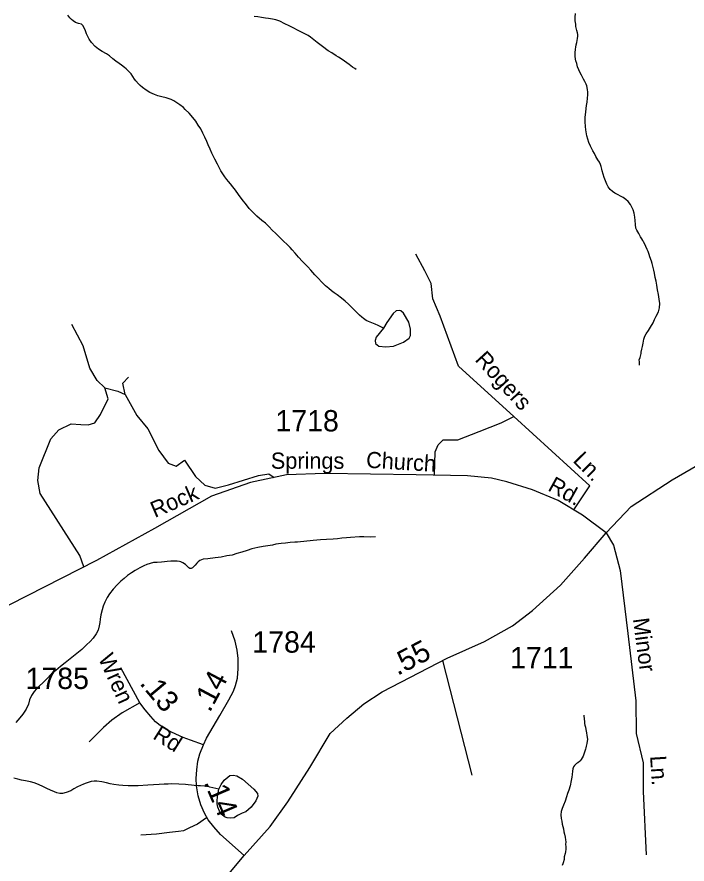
# Model space of a CAD drawing. Extents: x 2056842 to 2160602, y 826753 to 1016856.
# Drawn here: x 2112934 to 2116862, y 842001 to 846969 of the extents above; entities that cross this region are included whole.
import ezdxf

# ---------------------------------------------------------------- set-up
doc = ezdxf.new("R2010")
doc.units = 0
for name, color, linetype in [('Exist Hydrographic Misc Water Feature', 7, 'Continuous'), ('Exist Hydrographic Pond Under 1500 Sq Ft', 7, 'Continuous'), ('Exist Road Non-System Type 51', 7, 'Continuous'), ('Exist Road Non-System Type 51 Label', 7, 'Continuous'), ('Exist Road Secondary Mileage Hundredths English Label', 7, 'Continuous'), ('Exist Road Secondary Type 51 Attributed', 7, 'Continuous'), ('Exist Road Secondary Type 51 Label', 7, 'Continuous'), ('Exist Road Secondary Type 51 Number Label', 7, 'Continuous')]:
    doc.layers.add(name, color=color, linetype=linetype)

msp = doc.modelspace()

# ---------------------------------------------------------------- linework, layer by layer
at = {"layer": 'Exist Hydrographic Misc Water Feature'}
for points in [[(2113411.9, 846779.1), (2113392.1, 846796.3), (2113371.3, 846818.1), (2113357.2, 846838.1), (2113349, 846854.7), (2113341, 846870.5), (2113335.3, 846886.5), (2113328.9, 846904.5), (2113320.5, 846918.7), (2113312.9, 846926), (2113294.2, 846929.6), (2113276.6, 846935.9), (2113262.7, 846946.2), (2113254.1, 846953.5), (2113244.2, 846963.5), (2113232.5, 846979.5)], [(2114922.4, 846659.8), (2114914.6, 846665.9), (2114902.1, 846673.5), (2114882, 846689.5), (2114854.3, 846709.9), (2114839.7, 846719.1), (2114819.8, 846733.4), (2114805.5, 846741.3), (2114779.6, 846759), (2114759.5, 846770.9), (2114724.9, 846796.1), (2114693.1, 846819.5), (2114674.9, 846834.1), (2114654.6, 846850.1), (2114640.8, 846859.5), (2114610.3, 846875.5), (2114582.4, 846889.5), (2114554.3, 846904.7), (2114530.1, 846916.5), (2114504.1, 846928.5), (2114474.5, 846943.1), (2114451.8, 846951.8), (2114432.9, 846955.5), (2114409.7, 846959.4), (2114391.7, 846961.4), (2114367.7, 846965), (2114345.8, 846968.7), (2114325.7, 846971)], [(2116215.4, 846694.9), (2116211.3, 846711.3), (2116209.3, 846721.4), (2116207, 846739.2), (2116206.6, 846757.5), (2116208.7, 846779.5), (2116210.5, 846790.9), (2116212.5, 846804.9), (2116215.4, 846819.4), (2116218.1, 846830.8), (2116219.9, 846841.5), (2116222.2, 846855.3), (2116221.8, 846865.9), (2116219.9, 846875.2), (2116215.8, 846889.1), (2116211.3, 846913), (2116209.5, 846927), (2116207.4, 846945.2), (2116206.8, 846967.2), (2116208.9, 846989.2)], [(2115082.2, 845143.7), (2115067.7, 845151.2), (2115051.5, 845158.9), (2115033.7, 845166.5), (2115013.8, 845174.4), (2114995.4, 845182), (2114981.8, 845189), (2114966, 845199.8), (2114955.6, 845208.3), (2114943.1, 845220), (2114931.2, 845231.9), (2114912.7, 845249.3), (2114896.7, 845265.1), (2114878.5, 845283.7), (2114858.6, 845301.4), (2114836.4, 845318.9), (2114812, 845338.4), (2114794, 845350.1), (2114777.8, 845363), (2114761.8, 845376.5), (2114743.6, 845392.2), (2114721.4, 845414.2), (2114699.3, 845437.4), (2114681.2, 845456), (2114656.8, 845483.7), (2114639, 845503.4), (2114624.6, 845519.3), (2114608.4, 845535.2), (2114584.2, 845560.4), (2114566, 845583), (2114547.7, 845602), (2114535.8, 845616.4), (2114517.4, 845634.2), (2114497.5, 845654.3), (2114479, 845671.7), (2114451.2, 845697.8), (2114431.1, 845717.9), (2114412.6, 845736.9), (2114390.5, 845759), (2114370.6, 845774.9), (2114340.4, 845801), (2114318.1, 845822.6), (2114296.3, 845845.4), (2114279.5, 845866.2), (2114255.3, 845897.9), (2114232.8, 845927.7), (2114214.7, 845951.9), (2114200.6, 845971.9), (2114186.4, 845989.4), (2114174.5, 846003.8), (2114164.5, 846015.1), (2114152.2, 846031.2), (2114140.1, 846049.6), (2114130.2, 846066.9), (2114119.6, 846085.2), (2114109.7, 846104.9), (2114093.5, 846135), (2114076.9, 846170.4), (2114067.1, 846192.9), (2114054.6, 846218.4), (2114046.6, 846238.3), (2114036.3, 846264.1), (2114024.2, 846287.9), (2114011.7, 846312.1), (2113997.4, 846333.8), (2113983.2, 846357.8), (2113965.2, 846379.6), (2113943.2, 846403.6), (2113920.9, 846425.7), (2113911, 846437.3), (2113888.5, 846453.3), (2113872.3, 846465.1), (2113854.7, 846477.1), (2113838, 846484.5), (2113808.3, 846494.3), (2113784.1, 846499.5), (2113760.5, 846506), (2113740, 846513.9), (2113714, 846525.6), (2113691.6, 846539.5), (2113669.7, 846555.4), (2113656, 846567.2), (2113645.7, 846577.3), (2113631.6, 846594.8), (2113623.6, 846604.6), (2113613.1, 846618.8), (2113603.5, 846634.8), (2113594.2, 846645.5), (2113580.9, 846658.1), (2113574.8, 846663.9), (2113564.7, 846672.4), (2113546.5, 846686), (2113532.9, 846695.8), (2113514.3, 846709.6), (2113496.2, 846723.7), (2113476.5, 846739.7), (2113458.5, 846751.8), (2113433.9, 846765.2), (2113411.9, 846779.1)], [(2116582.9, 844926.2), (2116582.9, 844945.7), (2116582.7, 844958.2), (2116586.8, 844971.9), (2116592.5, 844994.1), (2116594.4, 845002.3), (2116598, 845020), (2116601.7, 845036.5), (2116605.8, 845056.2), (2116609.5, 845078.3), (2116615.5, 845096.1), (2116623.5, 845110.7), (2116636, 845130.3), (2116649.1, 845150.3), (2116663, 845174.5), (2116672.3, 845195), (2116682.3, 845214.6), (2116694.2, 845239.6), (2116700, 845263.5), (2116702, 845288.7), (2116699.8, 845313.4), (2116695.4, 845341.3), (2116688.9, 845368.6), (2116684.8, 845394.8), (2116680.7, 845418.9), (2116676.4, 845441.1), (2116672.1, 845466.5), (2116667.8, 845484.6), (2116657.7, 845522.6), (2116653.6, 845536.7), (2116645, 845562.3), (2116641.1, 845574.7), (2116634.8, 845592.7), (2116628.8, 845604.5), (2116620.8, 845622.8), (2116614.2, 845636.7), (2116606.7, 845650.1), (2116602.6, 845658.4), (2116598.3, 845666.7), (2116590.3, 845679.7), (2116584.3, 845690), (2116580, 845699.1), (2116574.3, 845708.1), (2116568.1, 845718), (2116563, 845730.5), (2116559.7, 845751.7), (2116557.4, 845775.6), (2116555.4, 845793.8), (2116552.1, 845817.8), (2116547, 845838), (2116539, 845853.8), (2116530.8, 845868.1), (2116518.1, 845887.1), (2116504.3, 845898.8), (2116488.1, 845909), (2116472.6, 845916.7), (2116457.8, 845925.4), (2116439.7, 845934.6), (2116426.2, 845944.8), (2116412.7, 845957.4), (2116400.6, 845972.6), (2116392.4, 845988.9), (2116384, 846007.2), (2116376.6, 846027.4), (2116370.4, 846046.1), (2116364.9, 846066.8), (2116362.6, 846076.5), (2116359.6, 846090.8), (2116354.4, 846103.7), (2116348.5, 846116.4), (2116340.3, 846130.2), (2116328.2, 846150.3), (2116319, 846168), (2116310.8, 846182.6), (2116295.8, 846210), (2116286.8, 846233.3), (2116281.2, 846251.1), (2116275.1, 846272), (2116268.7, 846305.8), (2116266.5, 846325.6), (2116264.4, 846353.6), (2116266.1, 846381.3), (2116270, 846409.9), (2116271.8, 846431.1), (2116273.7, 846449.9), (2116277.3, 846469.6), (2116279.4, 846491.7), (2116280.8, 846511.3), (2116280.2, 846527.6), (2116278.4, 846542.5), (2116274.5, 846564.2), (2116270.4, 846575.4), (2116264.2, 846589.7), (2116256, 846603.9), (2116247.8, 846619.3), (2116243.9, 846626.8), (2116233.5, 846645.1), (2116227.9, 846657.7), (2116221.2, 846675.7), (2116215.4, 846694.9)], [(2115082.2, 845143.7), (2115039.8, 845090.4), (2115033.6, 845070.3), (2115036.1, 845052.7), (2115056.2, 845038.9), (2115096.3, 845033.9), (2115141.5, 845038.9), (2115199.3, 845061.5), (2115233.2, 845085.4), (2115240.7, 845100.4), (2115242, 845136.9), (2115230.7, 845178.3), (2115199.3, 845232.4), (2115185.5, 845244.9), (2115176.7, 845247.4), (2115157.9, 845244.9), (2115139, 845228.6), (2115102.6, 845177.1), (2115082.2, 845143.7)], [(2115035.8, 843918.9), (2115007.7, 843918.7), (2114967.7, 843920.3), (2114941.6, 843920.2), (2114890, 843915.4), (2114865.8, 843913.4), (2114839.5, 843911.3), (2114814.1, 843908.7), (2114787.6, 843906.6), (2114748.3, 843904.5), (2114713.8, 843901.5), (2114669.7, 843897.6), (2114578.3, 843888.8), (2114564.1, 843888.5), (2114536.5, 843885.8), (2114508.4, 843882.4), (2114482.1, 843880.3), (2114452, 843875.9), (2114431.3, 843871.3), (2114404.6, 843867.2), (2114376.7, 843862.5), (2114346.4, 843857), (2114310.7, 843848.6), (2114282.8, 843840.2), (2114252.7, 843830.2), (2114222.9, 843821.7), (2114195, 843813), (2114164.9, 843807.4), (2114131.1, 843800.8), (2114097, 843796.1), (2114053.6, 843789.8), (2114025.3, 843788), (2114007.2, 843781.8), (2113997.4, 843773.9), (2113989.2, 843765.8), (2113979.5, 843753.5), (2113963.7, 843737.6), (2113955.3, 843733.7), (2113948.4, 843734.7), (2113941.8, 843738.9), (2113931.8, 843747.3), (2113921.5, 843757.4), (2113907.4, 843766.5), (2113895.1, 843772.8), (2113887.3, 843774.4), (2113873.7, 843776.5), (2113856.3, 843776.6), (2113835.4, 843776.1), (2113815.3, 843775.9), (2113799.3, 843773.9), (2113781, 843771.8), (2113755.6, 843769.5), (2113735.5, 843768.6), (2113715, 843763.1), (2113695.3, 843757.2), (2113677.5, 843749.3), (2113655.3, 843738.9), (2113627.9, 843722.4), (2113606.1, 843708.2), (2113582.1, 843692), (2113562.5, 843675.9), (2113542.4, 843659.5), (2113520.8, 843637.6), (2113498.5, 843613.3), (2113476.7, 843585), (2113463.4, 843563.5), (2113449.5, 843536.4), (2113439.6, 843513.1), (2113433.9, 843490.9), (2113426.1, 843462.4), (2113422.2, 843436.2), (2113420.6, 843418.2), (2113416.5, 843398.5), (2113411.1, 843372.6), (2113399, 843350.5), (2113381, 843326.4), (2113363.6, 843306.3), (2113342, 843286.1), (2113313.7, 843259.5), (2113276.2, 843227.5), (2113246.5, 843205.2), (2113216.9, 843180.5), (2113189.1, 843158.7), (2113161.2, 843136.6), (2113137.4, 843116.6), (2113109.7, 843087.6), (2113085.5, 843063.2), (2113065.8, 843046), (2113048, 843028.7), (2113034.2, 843012.9), (2113020.1, 842989.2), (2113008.6, 842963.3), (2113001.2, 842938.9), (2112987.3, 842908.9), (2112969.2, 842880.4), (2112951.6, 842858.7), (2112927.8, 842830.3)], [(2116258.1, 842873.2), (2116259.7, 842847.8), (2116260.3, 842838), (2116262, 842825.5), (2116264.2, 842815.9), (2116266.5, 842803.4), (2116268.7, 842789.2), (2116272.6, 842769.5), (2116274.7, 842753.9), (2116276.9, 842744.2), (2116278, 842731.9), (2116276.9, 842721.1), (2116275.1, 842707.9), (2116273.2, 842699.3), (2116271.6, 842691.8), (2116269.6, 842682), (2116267.7, 842673.7), (2116263.6, 842661.8), (2116257.9, 842645.2), (2116252.9, 842633.8), (2116247.4, 842623.2), (2116242.5, 842613.5), (2116236.3, 842605.5), (2116232.4, 842601.6), (2116222.2, 842593.4), (2116214.6, 842589.7), (2116206.8, 842583.2), (2116202.7, 842579.3), (2116196.8, 842571.3), (2116192.9, 842558.9), (2116190.6, 842545), (2116189.2, 842525.4), (2116187.5, 842510.6), (2116183.4, 842491), (2116177.7, 842459), (2116169.7, 842434.6), (2116162.5, 842414.2), (2116156, 842394.9), (2116147.5, 842370.2), (2116138.9, 842346.7), (2116130.9, 842326.5), (2116125.4, 842308.6), (2116123.1, 842290.3), (2116125.4, 842268.5), (2116127.5, 842252.7), (2116130.1, 842235.3), (2116133.6, 842220.6), (2116138.1, 842206.5), (2116140.8, 842189.9), (2116144.7, 842175.1), (2116148.4, 842158.7), (2116150.4, 842142.1), (2116151.4, 842130.7), (2116150.8, 842114.5), (2116151, 842102.7), (2116151.2, 842088.9), (2116149, 842072.6), (2116147.3, 842062.7), (2116143, 842042.2), (2116141.6, 842028.2), (2116135.7, 842008), (2116133.8, 842002.2), (2116129.7, 841992.7)], [(2114117.4, 842439.2), (2114064.8, 842451.9), (2114055.2, 842454.6), (2114046.8, 842456.3), (2114032.8, 842458.4), (2114009.3, 842459.6), (2113994.7, 842459.7), (2113973, 842461), (2113957, 842463), (2113938.7, 842464.9), (2113922.9, 842466.9), (2113882.7, 842468.6), (2113838.9, 842470.3), (2113821, 842469.8), (2113796.6, 842469.8), (2113767.1, 842467.8), (2113734.7, 842465), (2113701.1, 842462.4), (2113645.1, 842460.3), (2113622.9, 842460), (2113586.9, 842460.2), (2113555.3, 842461.4), (2113531.1, 842463.8), (2113502.8, 842467.7), (2113481.3, 842471.4), (2113458.7, 842476.4), (2113432, 842482.1), (2113402.5, 842486.1), (2113386.7, 842486.1), (2113369.5, 842484.2), (2113340.8, 842475.6), (2113325, 842469.5), (2113307.2, 842461.6), (2113288.7, 842453.1), (2113267.6, 842441.3), (2113249.3, 842431), (2113223.3, 842420.8), (2113200.7, 842414.9), (2113185.8, 842414.3), (2113167.3, 842418.7), (2113153.4, 842423.7), (2113131, 842433.1), (2113109.5, 842443.7), (2113089, 842453.7), (2113061.1, 842467.6), (2113034.9, 842477.3), (2113012.9, 842483.5), (2112984.8, 842488.9), (2112960.8, 842492.6), (2112938.7, 842498), (2112916.7, 842504.1)]]:
    msp.add_lwpolyline(points, dxfattribs=at)
at = {"layer": 'Exist Hydrographic Pond Under 1500 Sq Ft'}
msp.add_lwpolyline([(2114109.4, 842396), (2114117.4, 842439), (2114131, 842467.3), (2114149.1, 842492.2), (2114169.4, 842510.3), (2114181.9, 842520.5), (2114201.1, 842522.8), (2114223.8, 842518.2), (2114256.6, 842497.9), (2114322.3, 842440.2), (2114344.9, 842414.1), (2114346.1, 842399.4), (2114334.7, 842372.3), (2114306.4, 842333.8), (2114275.9, 842307.8), (2114254.4, 842299.9), (2114226.1, 842285.1), (2114206.8, 842271.6), (2114187.6, 842269.3), (2114166, 842271.6), (2114150.2, 842277.2), (2114135.5, 842291.9), (2114120.8, 842311.2), (2114111.7, 842333.8), (2114108.3, 842354.2), (2114107.2, 842368.9)], close=True, dxfattribs=at)
at = {"layer": 'Exist Road Non-System Type 51'}
msp.add_line((2115429.7, 843195.1), (2115601, 842521.2), dxfattribs=at)
for points in [[(2115847.2, 844625.6), (2115522.1, 844919.7), (2115415.1, 845213.8), (2115371.5, 845315.6), (2115363.2, 845405), (2115325.8, 845479.8), (2115271.8, 845577.5)], [(2113449.2, 844792.9), (2113403.6, 844836.6), (2113362, 844909.3), (2113322.6, 845040.2), (2113256.1, 845165)], [(2113568.7, 844754.5), (2113554.1, 844821), (2113587.4, 844856.3)], [(2113325.9, 843743.6), (2113302.8, 843810.8), (2113070.2, 844174.6), (2113055.7, 844249.4), (2113065, 844325.3), (2113133.5, 844493.6), (2113179.2, 844547.7), (2113251.9, 844583), (2113308, 844578.8), (2113351.6, 844576.8), (2113391.1, 844589.2), (2113424.3, 844637), (2113467.9, 844728.5), (2113449.2, 844792.9)], [(2113449.2, 844792.9), (2113525.1, 844773.2), (2113568.7, 844754.5)], [(2113568.7, 844754.5), (2113637.2, 844631.8), (2113701.6, 844552.8), (2113766, 844426.1), (2113820, 844351.2), (2113867.8, 844334.6), (2113915.5, 844369.9), (2113979.9, 844274.3), (2114036, 844222.4), (2114096.2, 844205.7), (2114175.2, 844224.5), (2114350.7, 844279.5), (2114410.9, 844289.9), (2114441.1, 844267.7)], [(2115382.7, 844281.3), (2115386.1, 844417.8), (2115402.7, 844459.3), (2115431.8, 844488.4), (2115519, 844488.4), (2115643.6, 844538.3), (2115772.4, 844588.2), (2115847.2, 844625.6)], [(2116198.8, 844077.5), (2116291.6, 844218.2), (2115847.2, 844625.6)], [(2116388.1, 843944.1), (2116430.8, 843871.1), (2116470.3, 843721.5), (2116516, 843353.6), (2116562.7, 842957.6), (2116564.8, 842766.4)], [(2113653.7, 842945.9), (2113551.8, 842887.9), (2113491.1, 842844), (2113442.4, 842801.6), (2113357.7, 842717)], [(2116564.8, 842766.4), (2116605, 842593.8), (2116605, 842426.2), (2116622.9, 842055.1)], [(2114045.4, 842271.2), (2113992.5, 842235.5), (2113946.3, 842213.1), (2113911.2, 842196.3), (2113880.4, 842190.7), (2113828.6, 842186.5), (2113751.5, 842176.7), (2113660.4, 842169.7)]]:
    msp.add_lwpolyline(points, dxfattribs=at)
at = {"layer": 'Exist Road Secondary Type 51 Attributed'}
for points in [[(2116388.1, 843944.1), (2116534.4, 844098.1), (2116774.8, 844255), (2117048.4, 844412.8), (2117278.4, 844500.3), (2117622.1, 844594.1)], [(2116388.1, 843944.1), (2116249.6, 844047.3), (2116106.3, 844132.5), (2115956.7, 844194.8), (2115805.1, 844242.6), (2115715.8, 844263.4), (2115574.5, 844278), (2115274.4, 844283.2), (2114738.6, 844291.5), (2114514.2, 844283.2), (2114303.4, 844238.5), (2114074.9, 844157.4), (2113740.5, 843968.3), (2113399.9, 843781.2), (2112788.2, 843470.5), (2112665.7, 843428.9), (2112414.4, 843389.4), (2112030.1, 843345.8), (2111796.5, 843290.7), (2111572.2, 843201.3), (2111246.1, 843072.5), (2110694.6, 842865.7), (2110385.1, 842772.1), (2109841, 842639.1)], [(2114265.5, 842051.4), (2114418.7, 842221.4), (2114522.5, 842365.8), (2114650.8, 842566.9), (2114770.2, 842766.4), (2114868.4, 842856.3), (2114967, 842940.5), (2115075, 843010.1), (2115456.7, 843209.1), (2115674.8, 843305.8), (2115839.9, 843398.3), (2115956.7, 843488.2), (2116120.8, 843635.7), (2116262, 843793.7), (2116388.1, 843944.1)], [(2114027.3, 842700.3), (2114046.2, 842739.9), (2114124.4, 842871.7), (2114175.5, 842962.9), (2114203.6, 843015.6), (2114215.6, 843048.7), (2114226.7, 843091.8), (2114231.7, 843147.7), (2114230.7, 843205.8), (2114224.7, 843254.9), (2114213.6, 843308), (2114192.6, 843369.1)], [(2114027.3, 842700.3), (2113951.8, 842726.4), (2113909.4, 842743.6), (2113865.5, 842762.4), (2113835.7, 842776.5), (2113813.8, 842787.5), (2113773, 842812.6), (2113746.3, 842834.5), (2113718.1, 842865.9), (2113685.1, 842905.1), (2113653.7, 842945.9), (2113542.4, 843151.2)], [(2114265.5, 842051.4), (2114128.3, 842174.4), (2114088.2, 842219.2), (2114055.3, 842259.2), (2114034, 842299.2), (2114012.8, 842348.7), (2113996.3, 842400.5), (2113987, 842460.3), (2113985, 842502.4), (2113988, 842552.5), (2113995, 842603.6), (2114007.1, 842647.7), (2114027.3, 842700.3)], [(2110161.3, 837925.3), (2110240.8, 838012.5), (2110290.6, 838084.2), (2110484.3, 838398.6), (2110551.8, 838506.6), (2110666.1, 838648), (2111061.2, 838947.8), (2111342.6, 839162.9), (2111828.1, 839517.8), (2112005.7, 839648.8), (2112153.2, 839776.6), (2112414.4, 840055.6), (2112605.5, 840270.7), (2112765.4, 840428.7), (2112979.8, 840595.5), (2113315.3, 840860.5), (2113545.3, 841077.2), (2113674.1, 841251.8), (2113879.2, 841571.3), (2114035, 841775), (2114265.5, 842051.4)]]:
    msp.add_lwpolyline(points, dxfattribs=at)

# ---------------------------------------------------------------- texts
at = {"layer": 'Exist Road Non-System Type 51 Label'}
for s, rotation, p in [('Rogers', 312.4199, (2115614.2, 844955.6)), ('Ln.', 314.9748, (2116188.7, 844362.4)), ('Minor', 277.5193, (2116544.6, 843439)), ('Ln.', 273.6868, (2116645.7, 842634.3))]:
    msp.add_text(s, height=95, rotation=rotation, dxfattribs=at).set_placement(p)
at = {"layer": 'Exist Road Secondary Mileage Hundredths English Label'}
for s, rotation, p in [('.55', 27.5398, (2115165.2, 843103.3)), ('.14', 61.9596, (2114064.5, 842885.1)), ('.13', 310.0464, (2113648.8, 843058.8)), ('.14', 293.2105, (2114027.9, 842480.1))]:
    msp.add_text(s, height=125, rotation=rotation, dxfattribs=at).set_placement(p)
at = {"layer": 'Exist Road Secondary Type 51 Label'}
for s, rotation, p in [('Springs', 359.9256, (2114422.4, 844319.1)), ('Church', 356.5564, (2114978.9, 844325.4)), ('Rd.', 330.7818, (2116040.5, 844195.1)), ('Rock', 23.3194, (2113742.4, 844029.5)), ('Wren', 294.5376, (2113408.8, 843208.6)), ('Rd', 327.8154, (2113724.8, 842739.3))]:
    msp.add_text(s, height=95, rotation=rotation, dxfattribs=at).set_placement(p)
at = {"layer": 'Exist Road Secondary Type 51 Number Label'}
for s, p in [('1718', (2114449.2, 844538)), ('1784', (2114313.9, 843240.6)), ('1711', (2115824.9, 843148.9)), ('1785', (2112984.4, 843027.5))]:
    msp.add_text(s, height=125, dxfattribs=at).set_placement(p)

doc.saveas('drawing.dxf')
